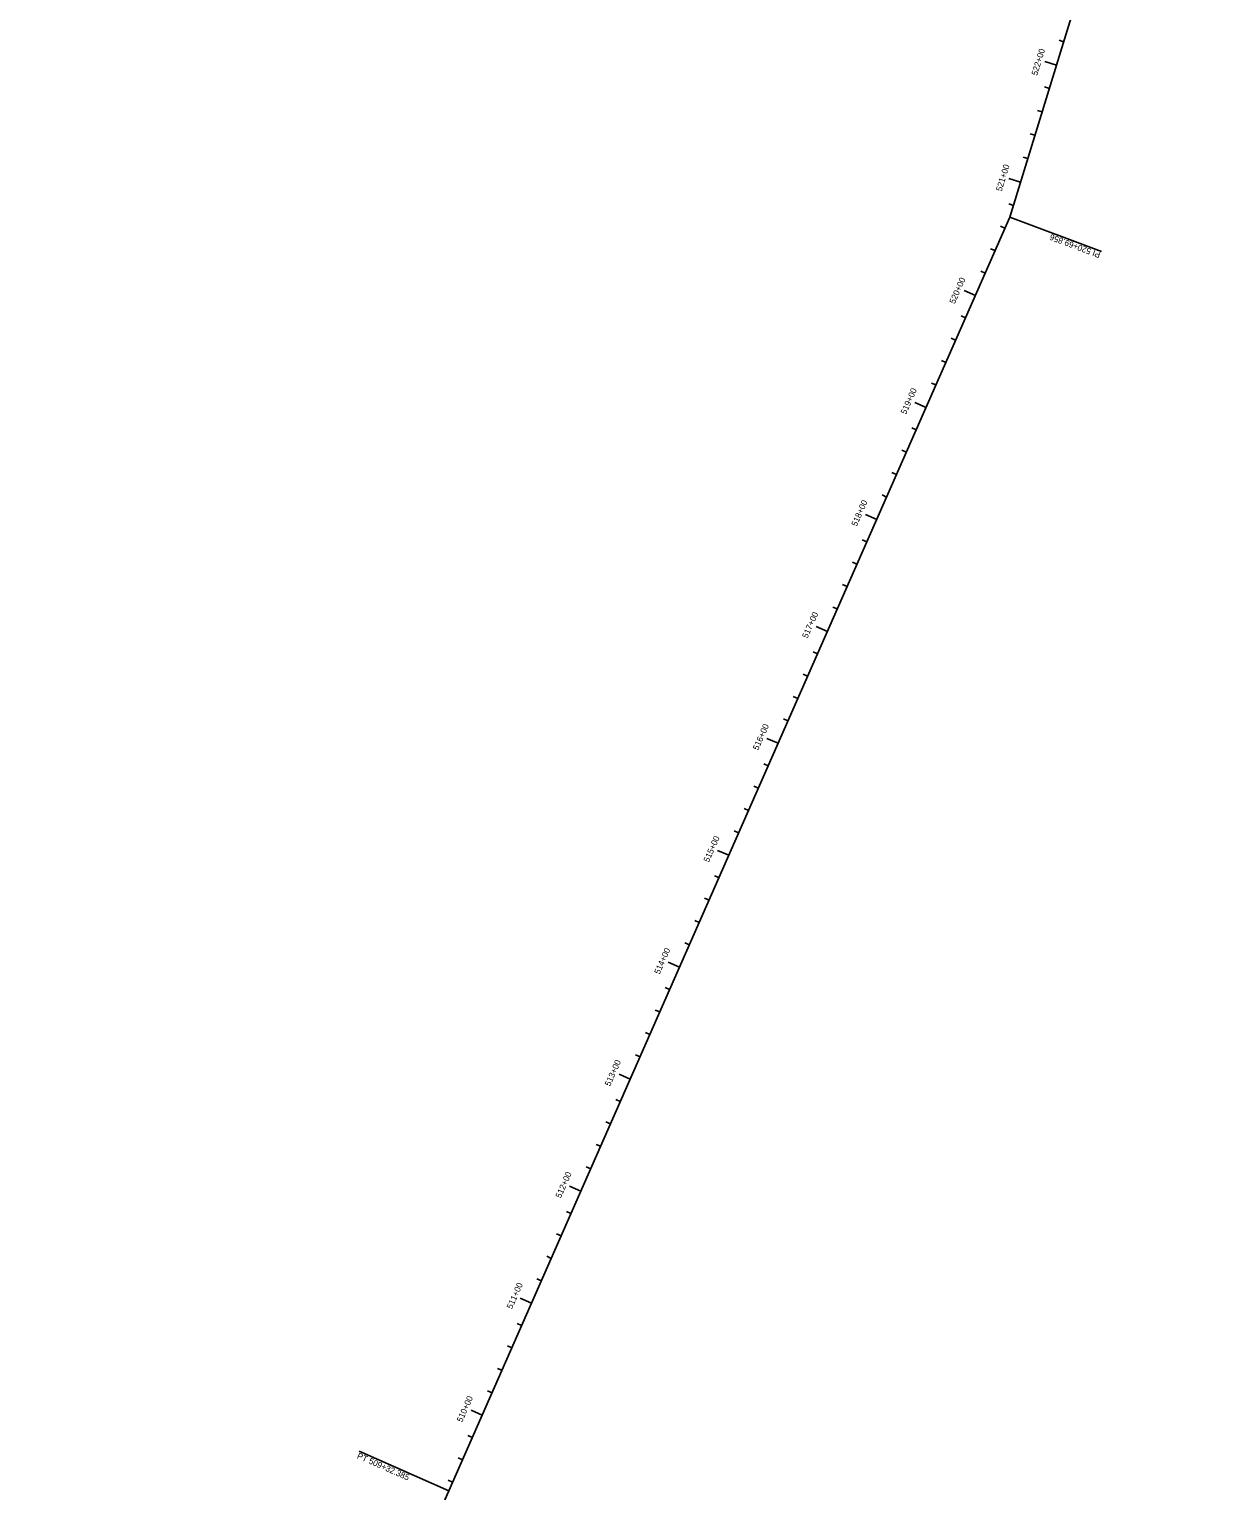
# Model space of a CAD drawing. Extents: x 187748 to 191086, y 249974 to 259749.
# Drawn here: x 189932 to 190913, y 257351 to 258546 of the extents above; entities that cross this region are included whole.
import ezdxf

# ---------------------------------------------------------------- set-up
doc = ezdxf.new("R2010")
doc.units = 0
doc.layers.add('BORDER', color=7, linetype='Continuous')

msp = doc.modelspace()

# ---------------------------------------------------------------- linework, layer by layer
at = {"layer": 'BORDER'}
for p, q in [((190733.3, 258392.2), (190913.1, 258978.7)), ((190777.3, 258535.7), (190773.5, 258536.9)), ((190771.4, 258516.6), (190761.9, 258519.6)), ((190765.6, 258497.5), (190761.7, 258498.7)), ((190759.7, 258478.4), (190755.9, 258479.5)), ((190753.8, 258459.3), (190750, 258460.4)), ((190748, 258440.1), (190744.1, 258441.3)), ((190742.1, 258421), (190732.5, 258423.9)), ((190736.2, 258401.9), (190732.4, 258403.1)), ((190274.7, 257351.2), (190733.3, 258392.2)), ((190733.3, 258392.2), (190808.2, 258364.3)), ((190729.3, 258383.2), (190725.6, 258384.8)), ((190721.2, 258364.9), (190717.6, 258366.5)), ((190713.2, 258346.6), (190709.5, 258348.2)), ((190705.1, 258328.3), (190695.9, 258332.3)), ((190697, 258310), (190693.4, 258311.6)), ((190689, 258291.7), (190685.3, 258293.3)), ((190680.9, 258273.4), (190677.3, 258275)), ((190672.8, 258255.1), (190669.2, 258256.7)), ((190664.8, 258236.8), (190655.6, 258240.8)), ((190656.7, 258218.4), (190653.1, 258220.1)), ((190648.7, 258200.1), (190645, 258201.8)), ((190640.6, 258181.8), (190636.9, 258183.5)), ((190632.5, 258163.5), (190628.9, 258165.2)), ((190624.5, 258145.2), (190615.3, 258149.3)), ((190616.4, 258126.9), (190612.7, 258128.5)), ((190608.3, 258108.6), (190604.7, 258110.2)), ((190600.3, 258090.3), (190596.6, 258091.9)), ((190592.2, 258072), (190588.6, 258073.6)), ((190584.2, 258053.7), (190575, 258057.8)), ((190576.1, 258035.4), (190572.4, 258037)), ((190568, 258017.1), (190564.4, 258018.7)), ((190560, 257998.8), (190556.3, 258000.4)), ((190551.9, 257980.5), (190548.2, 257982.1)), ((190543.8, 257962.2), (190534.7, 257966.2)), ((190535.8, 257943.9), (190532.1, 257945.5)), ((190527.7, 257925.6), (190524.1, 257927.2)), ((190519.7, 257907.3), (190516, 257908.9)), ((190511.6, 257889), (190507.9, 257890.6)), ((190503.5, 257870.7), (190494.4, 257874.7)), ((190495.5, 257852.4), (190491.8, 257854)), ((190487.4, 257834.1), (190483.7, 257835.7)), ((190479.3, 257815.8), (190475.7, 257817.4)), ((190471.3, 257797.5), (190467.6, 257799.1)), ((190463.2, 257779.2), (190454.1, 257783.2)), ((190455.2, 257760.9), (190451.5, 257762.5)), ((190447.1, 257742.6), (190443.4, 257744.2)), ((190439, 257724.3), (190435.4, 257725.9)), ((190431, 257706), (190427.3, 257707.6)), ((190422.9, 257687.7), (190413.8, 257691.7)), ((190414.8, 257669.4), (190411.2, 257671)), ((190406.8, 257651.1), (190403.1, 257652.7)), ((190398.7, 257632.8), (190395.1, 257634.4)), ((190390.7, 257614.5), (190387, 257616.1)), ((190382.6, 257596.2), (190373.4, 257600.2)), ((190374.5, 257577.8), (190370.9, 257579.5)), ((190366.5, 257559.5), (190362.8, 257561.2)), ((190358.4, 257541.2), (190354.7, 257542.9)), ((190350.3, 257522.9), (190346.7, 257524.6)), ((190342.3, 257504.6), (190333.1, 257508.7)), ((190334.2, 257486.3), (190330.6, 257487.9)), ((190326.2, 257468), (190322.5, 257469.6)), ((190318.1, 257449.7), (190314.4, 257451.3)), ((190310, 257431.4), (190306.4, 257433)), ((190302, 257413.1), (190292.8, 257417.2)), ((190293.9, 257394.8), (190290.2, 257396.4)), ((190274.7, 257351.2), (190201.5, 257383.5)), ((190285.8, 257376.5), (190282.2, 257378.1)), ((190277.8, 257358.2), (190274.1, 257359.8))]:
    msp.add_line(p, q, dxfattribs=at)
msp.add_lwpolyline([(189931.6, 256692), (190124.6, 257010.5), (190274.7, 257351.2)], dxfattribs=at)

# ---------------------------------------------------------------- texts
for s, rotation, p in [('522+00', 72.9522, (190755.6, 258507.6)), ('521+00', 72.9522, (190726.6, 258413)), ('PI 520+69.856', 159.589, (190807.9, 258363.4)), ('520+00', 66.2258, (190688.2, 258321)), ('519+00', 66.2258, (190648.4, 258230.6)), ('518+00', 66.2258, (190608.1, 258139.1)), ('517+00', 66.2258, (190567.8, 258047.6)), ('516+00', 66.2258, (190527.5, 257956.1)), ('515+00', 66.2258, (190487.2, 257864.5)), ('514+00', 66.2258, (190446.9, 257773)), ('513+00', 66.2258, (190406.5, 257681.5)), ('512+00', 66.2258, (190366.2, 257590)), ('511+00', 66.2258, (190326.3, 257499.4)), ('510+00', 66.2258, (190285.5, 257406.8)), ('PT 509+32.385', 336.2258, (190199.1, 257378))]:
    msp.add_text(s, height=5, rotation=rotation, dxfattribs=at).set_placement(p)

doc.saveas('drawing.dxf')
